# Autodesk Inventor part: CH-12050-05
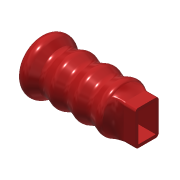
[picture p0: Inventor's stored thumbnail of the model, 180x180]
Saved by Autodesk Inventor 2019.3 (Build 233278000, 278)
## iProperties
Created: 2015-08
Part Number: CH-12050-05
Material: Ogólny
Document SubType Name: Modeling
Designer: CADENGINEERING4
Density: 1 g/cm^3
Appearance: Jasnoczerwona
Author: CADENGINEERING4
Revision Number: ÈÎºÎ
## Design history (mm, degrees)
feature "ÇÐ³ý-À­Éì1"
node "Bryła1"
